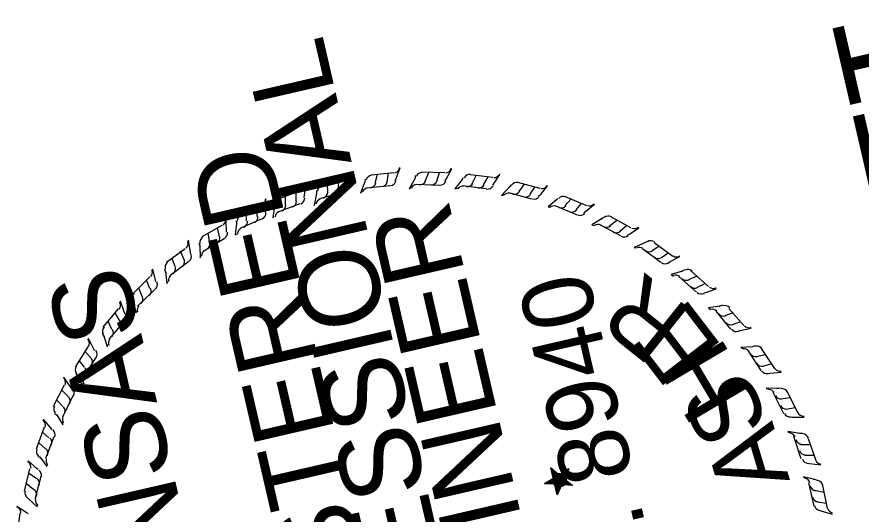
# Model space of a CAD drawing. Extents: x 634644 to 1109343, y 286699 to 700411.
# Drawn here: x 1108872.2 to 1108970.3, y 700241.6 to 700299.3 of the extents above; entities that cross this region are included whole.
import ezdxf

# ---------------------------------------------------------------- set-up
doc = ezdxf.new("R2010")
doc.units = 0
doc.layers.add('S_GAS_UTILITIES', color=7, linetype='Continuous')
doc.layers.add('S_PRIMARY_CTL', color=7, linetype='Continuous')

msp = doc.modelspace()

# ---------------------------------------------------------------- linework, layer by layer
at = {"layer": 'S_PRIMARY_CTL'}
for p, q in [((1108916.259, 700280.557), (1108916.717, 700281.771)), ((1108916.717, 700281.771), (1108916.555, 700281.672)), ((1108922.065, 700280.481), (1108922.712, 700281.677)), ((1108922.712, 700281.677), (1108922.537, 700281.637)), ((1108910.511, 700279.846), (1108910.768, 700281.136)), ((1108910.768, 700281.136), (1108910.651, 700281.109)), ((1108913.327, 700280.988), (1108915.98, 700281.231)), ((1108913.803, 700279.99), (1108914.055, 700281.033)), ((1108915.188, 700280.125), (1108915.368, 700281.213)), ((1108918.462, 700280.881), (1108918.471, 700280.575)), ((1108919.227, 700281.304), (1108921.889, 700281.241)), ((1108919.6, 700280.22), (1108920.041, 700281.245)), ((1108920.954, 700280.224), (1108921.278, 700281.223)), ((1108924.003, 700280.62), (1108923.926, 700280.418)), ((1108924.839, 700280.998), (1108927.497, 700280.688)), ((1108925.082, 700279.946), (1108925.536, 700280.913)), ((1108926.404, 700279.82), (1108926.931, 700280.742)), ((1108927.556, 700279.901), (1108928.289, 700280.994)), ((1108928.289, 700280.994), (1108928.172, 700280.967)), ((1108905.583, 700278.523), (1108905.708, 700279.845)), ((1108905.708, 700279.845), (1108905.605, 700279.76)), ((1108907.57, 700279.782), (1108910.161, 700280.565)), ((1108908.281, 700278.838), (1108908.258, 700280.003)), ((1108909.527, 700279.31), (1108909.589, 700280.372)), ((1108910.448, 700279.585), (1108910.511, 700279.846)), ((1108912.598, 700280.143), (1108912.095, 700278.856)), ((1108912.598, 700280.143), (1108912.567, 700280.012)), ((1108912.648, 700280.462), (1108912.598, 700280.143)), ((1108915.53, 700279.711), (1108912.76, 700279.441)), ((1108916.137, 700280.282), (1108916.259, 700280.557)), ((1108918.471, 700280.575), (1108917.765, 700279.365)), ((1108918.471, 700280.575), (1108918.381, 700280.431)), ((1108921.309, 700279.752), (1108918.516, 700279.846)), ((1108921.93, 700280.265), (1108922.065, 700280.481)), ((1108923.926, 700280.418), (1108923.063, 700279.357)), ((1108923.926, 700280.418), (1108923.895, 700280.288)), ((1108926.701, 700279.335), (1108923.972, 700279.69)), ((1108927.466, 700279.757), (1108927.556, 700279.901)), ((1108929.606, 700279.82), (1108929.472, 700279.605)), ((1108930.339, 700280.113), (1108932.961, 700279.425)), ((1108930.524, 700279.047), (1108931.135, 700279.866)), ((1108933.02, 700278.638), (1108933.825, 700279.686)), ((1108933.825, 700279.686), (1108933.649, 700279.645)), ((1108902.695, 700278.226), (1108905.245, 700279.184)), ((1108904.625, 700277.871), (1108904.629, 700278.919)), ((1108906.999, 700278.789), (1108906.698, 700277.426)), ((1108906.999, 700278.789), (1108906.954, 700278.717)), ((1108906.977, 700279.153), (1108906.999, 700278.789)), ((1108909.927, 700278.91), (1108907.323, 700278.186)), ((1108912.095, 700278.856), (1108912.301, 700279.027)), ((1108917.765, 700279.365), (1108917.972, 700279.536)), ((1108923.063, 700279.357), (1108923.355, 700279.424)), ((1108929.472, 700279.605), (1108928.478, 700278.575)), ((1108932.022, 700278.161), (1108929.328, 700278.894)), ((1108929.472, 700279.605), (1108929.368, 700279.519)), ((1108931.828, 700278.732), (1108932.381, 700279.537)), ((1108901.108, 700278.167), (1108901.005, 700278.082)), ((1108901.041, 700276.859), (1108901.108, 700278.167)), ((1108903.366, 700277.457), (1108903.37, 700278.505)), ((1108905.506, 700278.321), (1108905.583, 700278.523)), ((1108906.698, 700277.426), (1108906.819, 700277.7)), ((1108928.478, 700278.575), (1108928.77, 700278.642)), ((1108932.8, 700278.526), (1108933.02, 700278.638)), ((1108934.873, 700278.081), (1108933.897, 700277.24)), ((1108934.873, 700278.081), (1108934.783, 700277.937)), ((1108935.021, 700278.238), (1108934.873, 700278.081)), ((1108935.835, 700277.379), (1108936.577, 700278.166)), ((1108935.898, 700278.44), (1108938.354, 700277.406)), ((1108898.194, 700276.386), (1108900.6, 700277.434)), ((1108900.096, 700276.148), (1108900.042, 700277.182)), ((1108901.036, 700276.611), (1108901.041, 700276.859)), ((1108902.111, 700277.29), (1108901.913, 700276.013)), ((1108902.102, 700277.596), (1108902.111, 700277.29)), ((1108902.111, 700277.29), (1108902.138, 700277.174)), ((1108905.057, 700277.601), (1108902.507, 700276.643)), ((1108933.897, 700277.24), (1108934.086, 700277.222)), ((1108937.315, 700276.304), (1108934.729, 700277.37)), ((1108937.18, 700276.889), (1108937.805, 700277.649)), ((1108938.075, 700276.48), (1108938.268, 700276.709)), ((1108938.268, 700276.709), (1108939.303, 700277.564)), ((1108939.303, 700277.564), (1108939.127, 700277.523)), ((1108896.44, 700275.981), (1108896.364, 700275.779)), ((1108896.517, 700274.583), (1108896.44, 700275.981)), ((1108900.658, 700275.847), (1108898.136, 700274.772)), ((1108898.864, 700275.617), (1108898.81, 700276.652)), ((1108901.913, 700276.013), (1108902.075, 700276.112)), ((1108940.175, 700275.918), (1108938.997, 700275.153)), ((1108940.175, 700275.918), (1108940.085, 700275.774)), ((1108940.337, 700276.017), (1108940.175, 700275.918)), ((1108941.241, 700276.102), (1108943.503, 700274.839)), ((1108893.679, 700273.804), (1108896.017, 700275.145)), ((1108895.716, 700273.782), (1108895.473, 700274.834)), ((1108897.695, 700275.347), (1108897.511, 700274.012)), ((1108897.627, 700275.64), (1108897.695, 700275.347)), ((1108897.695, 700275.347), (1108897.722, 700275.23)), ((1108938.997, 700275.153), (1108939.258, 700275.09)), ((1108942.366, 700273.899), (1108939.914, 700275.18)), ((1108941.003, 700275.001), (1108941.889, 700275.698)), ((1108942.244, 700274.425), (1108943.013, 700275.095)), ((1108943.373, 700274.07), (1108944.434, 700274.808)), ((1108944.434, 700274.808), (1108944.304, 700274.839)), ((1108894.583, 700273.089), (1108894.385, 700274.214)), ((1108896.512, 700274.335), (1108896.517, 700274.583)), ((1108897.511, 700274.012), (1108897.789, 700274.138)), ((1108943.153, 700273.957), (1108943.373, 700274.07)), ((1108892.114, 700273.382), (1108891.979, 700273.166)), ((1108892.321, 700271.951), (1108892.114, 700273.382)), ((1108893.301, 700273.04), (1108893.427, 700272.761)), ((1108896.265, 700273.539), (1108893.882, 700272.127)), ((1108945.145, 700273.063), (1108943.913, 700272.532)), ((1108945.145, 700273.063), (1108945.028, 700273.036)), ((1108945.41, 700273.247), (1108945.145, 700273.063)), ((1108946.238, 700273.13), (1108948.392, 700271.534)), ((1108889.564, 700270.822), (1108891.718, 700272.428)), ((1108891.593, 700271.106), (1108891.174, 700272.118)), ((1108892.362, 700271.776), (1108892.321, 700271.951)), ((1108893.427, 700272.761), (1108893.396, 700272.631)), ((1108893.427, 700272.761), (1108893.445, 700271.349)), ((1108943.913, 700272.532), (1108944.102, 700272.514)), ((1108947.025, 700270.787), (1108944.871, 700272.384)), ((1108945.972, 700272.145), (1108946.827, 700272.712)), ((1108947.079, 700271.354), (1108947.875, 700271.907)), ((1108892.128, 700270.922), (1108889.929, 700269.244)), ((1108890.545, 700270.31), (1108890.185, 700271.335)), ((1108893.445, 700271.349), (1108893.567, 700271.623)), ((1108947.839, 700270.729), (1108948.104, 700270.913)), ((1108948.104, 700270.913), (1108949.206, 700271.476)), ((1108949.206, 700271.476), (1108949.134, 700271.521)), ((1108887.963, 700270.022), (1108887.815, 700269.864)), ((1108888.26, 700268.736), (1108887.963, 700270.022)), ((1108889.259, 700270.013), (1108889.443, 700269.748)), ((1108949.746, 700269.938), (1108949.539, 700269.767)), ((1108885.715, 700267.224), (1108887.613, 700269.14)), ((1108889.443, 700269.748), (1108889.578, 700268.362)), ((1108889.443, 700269.748), (1108889.47, 700269.631)), ((1108949.539, 700269.767), (1108948.208, 700269.398)), ((1108948.208, 700269.398), (1108948.496, 700269.218)), ((1108951.14, 700267.365), (1108949.121, 700269.177)), ((1108949.539, 700269.767), (1108949.364, 700269.726)), ((1108950.25, 700268.822), (1108951.144, 700269.214)), ((1108950.515, 700269.807), (1108952.534, 700267.995)), ((1108887.617, 700267.787), (1108887.213, 700268.74)), ((1108888.301, 700268.56), (1108888.26, 700268.736)), ((1108889.578, 700268.362), (1108889.7, 700268.637)), ((1108951.208, 700267.874), (1108952.089, 700268.323)), ((1108953.461, 700267.716), (1108953.303, 700267.865)), ((1108888.198, 700267.674), (1108886.183, 700265.731)), ((1108886.727, 700266.842), (1108886.322, 700267.795)), ((1108952.026, 700267.262), (1108952.26, 700267.316)), ((1108952.26, 700267.316), (1108953.461, 700267.716)), ((1108884.2, 700266.32), (1108884.065, 700266.104)), ((1108884.614, 700265.061), (1108884.2, 700266.32)), ((1108885.54, 700266.383), (1108885.697, 700266.235)), ((1108885.697, 700266.235), (1108885.666, 700266.104)), ((1108885.697, 700266.235), (1108885.994, 700264.949)), ((1108882.194, 700263.271), (1108883.979, 700265.407)), ((1108884.114, 700264.022), (1108883.593, 700264.948)), ((1108884.739, 700264.782), (1108884.614, 700265.061)), ((1108885.994, 700264.949), (1108886.143, 700265.106)), ((1108953.861, 700265.715), (1108952.548, 700265.535)), ((1108952.548, 700265.535), (1108952.777, 700265.342)), ((1108955.152, 700263.057), (1108953.443, 700265.126)), ((1108953.861, 700265.715), (1108953.758, 700265.63)), ((1108954.14, 700265.841), (1108953.861, 700265.715)), ((1108954.482, 700264.627), (1108955.449, 700264.973)), ((1108954.904, 700265.463), (1108956.659, 700263.467)), ((1108884.668, 700264.027), (1108882.824, 700261.877)), ((1108955.336, 700263.593), (1108956.303, 700263.939)), ((1108883.179, 700263.006), (1108882.788, 700263.901)), ((1108956.24, 700262.878), (1108957.527, 700263.175)), ((1108957.527, 700263.175), (1108957.383, 700263.264)), ((1108882.064, 700262.502), (1108882.248, 700262.237)), ((1108882.248, 700262.237), (1108882.649, 700261.036)), ((1108882.248, 700262.237), (1108882.32, 700262.192)), ((1108956.007, 700262.824), (1108956.24, 700262.878)), ((1108878.997, 700258.715), (1108880.436, 700261.018)), ((1108880.467, 700261.949), (1108880.378, 700261.805)), ((1108881.115, 700260.743), (1108880.467, 700261.949)), ((1108882.649, 700261.036), (1108882.784, 700261.252)), ((1108957.662, 700260.989), (1108956.321, 700260.926)), ((1108957.662, 700260.989), (1108957.486, 700260.948)), ((1108957.94, 700261.115), (1108957.662, 700260.989)), ((1108880.733, 700259.731), (1108880.063, 700260.5)), ((1108881.214, 700260.582), (1108881.115, 700260.743)), ((1108956.321, 700260.926), (1108956.537, 700260.791)), ((1108958.66, 700258.264), (1108957.145, 700260.562)), ((1108958.107, 700259.86), (1108959.159, 700260.103)), ((1108958.692, 700260.796), (1108960.207, 700258.498)), ((1108880, 700258.639), (1108879.388, 700259.421)), ((1108881.286, 700259.736), (1108879.802, 700257.361)), ((1108958.858, 700258.74), (1108959.838, 700259.028)), ((1108959.717, 700257.954), (1108960.985, 700258.062)), ((1108960.985, 700258.062), (1108960.886, 700258.223)), ((1108877.621, 700257.474), (1108877.603, 700257.285)), ((1108878.372, 700256.354), (1108877.621, 700257.474)), ((1108878.997, 700257.914), (1108879.11, 700257.694)), ((1108879.11, 700257.694), (1108879.744, 700256.547)), ((1108879.11, 700257.694), (1108879.254, 700257.604)), ((1108959.425, 700257.886), (1108959.717, 700257.954)), ((1108876.425, 700254.119), (1108877.707, 700256.57)), ((1108878.543, 700256.147), (1108878.372, 700256.354)), ((1108879.744, 700256.547), (1108879.879, 700256.763)), ((1108960.689, 700256.146), (1108959.263, 700256.186)), ((1108959.263, 700256.186), (1108959.537, 700256.065)), ((1108960.689, 700256.146), (1108960.513, 700256.105)), ((1108960.981, 700256.213), (1108960.689, 700256.146)), ((1108878.134, 700255.252), (1108877.347, 700255.994)), ((1108878.674, 700255.315), (1108877.464, 700252.819)), ((1108961.305, 700253.209), (1108960.055, 700255.691)), ((1108960.959, 700254.977), (1108962.038, 700255.103)), ((1108961.701, 700255.764), (1108962.938, 700253.34)), ((1108877.487, 700254.056), (1108876.816, 700254.825)), ((1108876.511, 700253.215), (1108876.785, 700253.093)), ((1108961.548, 700253.758), (1108962.614, 700253.942)), ((1108875.247, 700252.553), (1108875.171, 700252.351)), ((1108876.088, 700251.578), (1108875.247, 700252.553)), ((1108876.785, 700253.093), (1108877.478, 700251.96)), ((1108876.785, 700253.093), (1108876.812, 700252.976)), ((1108877.478, 700251.96), (1108877.482, 700252.207)), ((1108962.056, 700252.89), (1108962.317, 700252.827)), ((1108962.317, 700252.827), (1108963.671, 700252.832)), ((1108963.671, 700252.832), (1108963.513, 700252.98)), ((1108874.429, 700249.163), (1108875.378, 700251.722)), ((1108876.259, 700251.371), (1108876.088, 700251.578)), ((1108875.863, 700250.417), (1108875.162, 700251.056)), ((1108876.448, 700250.552), (1108875.486, 700248.052)), ((1108963.185, 700250.934), (1108961.777, 700251.163)), ((1108961.777, 700251.163), (1108961.993, 700251.028)), ((1108963.307, 700248.006), (1108962.466, 700250.583)), ((1108963.185, 700250.934), (1108963.055, 700250.965)), ((1108963.491, 700250.943), (1108963.185, 700250.934)), ((1108964.121, 700250.349), (1108965.02, 700247.786)), ((1108875.477, 700249.158), (1108874.703, 700249.842)), ((1108963.235, 700249.652), (1108964.399, 700249.675)), ((1108874.573, 700248.272), (1108874.834, 700248.209)), ((1108963.707, 700248.406), (1108964.755, 700248.402)), ((1108873.458, 700247.768), (1108873.44, 700247.579)), ((1108874.461, 700246.891), (1108873.458, 700247.768)), ((1108874.834, 700248.209), (1108875.643, 700247.103)), ((1108874.834, 700248.209), (1108874.874, 700248.034)), ((1108875.643, 700247.103), (1108875.661, 700247.292)), ((1108964.04, 700247.498), (1108964.301, 700247.435)), ((1108964.301, 700247.435), (1108965.623, 700247.309)), ((1108965.623, 700247.309), (1108965.537, 700247.413)), ((1108873.044, 700244.224), (1108873.674, 700246.833)), ((1108874.425, 700245.713), (1108873.548, 700246.311)), ((1108874.618, 700246.743), (1108874.461, 700246.891)), ((1108934.237, 700246.96), (1108935.186, 700245.517)), ((1108934.237, 700246.96), (1108934.723, 700245.656)), ((1108934.237, 700246.96), (1108934.826, 700245.741)), ((1108934.237, 700246.96), (1108934.885, 700245.755)), ((1108934.237, 700246.96), (1108934.934, 700246.074)), ((1108934.237, 700246.96), (1108934.966, 700246.205)), ((1108934.237, 700246.96), (1108935.011, 700246.277)), ((1108936.301, 700246.821), (1108935.078, 700245.984)), ((1108936.301, 700246.821), (1108935.105, 700245.867)), ((1108936.301, 700246.821), (1108935.186, 700245.517)), ((1108936.301, 700246.821), (1108935.339, 700245.921)), ((1108936.301, 700246.821), (1108935.483, 700245.831)), ((1108936.301, 700246.821), (1108935.537, 700245.597)), ((1108936.301, 700246.821), (1108935.654, 700245.624)), ((1108874.924, 700245.952), (1108874.25, 700243.271)), ((1108933.491, 700245.125), (1108934.534, 700245.674)), ((1108933.491, 700245.125), (1108934.534, 700245.674)), ((1108935.186, 700245.517), (1108933.491, 700245.125)), ((1108933.491, 700245.125), (1108934.575, 700245.498)), ((1108933.491, 700245.125), (1108934.602, 700245.382)), ((1108934.966, 700243.803), (1108935.186, 700245.517)), ((1108936.747, 700244.892), (1108935.186, 700245.517)), ((1108936.747, 700244.892), (1108935.537, 700245.597)), ((1108936.747, 700244.892), (1108935.546, 700245.292)), ((1108936.747, 700244.892), (1108935.577, 700245.422)), ((1108936.747, 700244.892), (1108935.64, 700245.683)), ((1108964.908, 700245.605), (1108963.604, 700245.919)), ((1108963.604, 700245.919), (1108963.761, 700245.771)), ((1108964.908, 700245.605), (1108964.733, 700245.564)), ((1108965.241, 700245.497), (1108964.908, 700245.605)), ((1108874.11, 700244.409), (1108873.278, 700245.079)), ((1108933.491, 700245.125), (1108934.642, 700245.206)), ((1108933.491, 700245.125), (1108934.656, 700245.148)), ((1108934.966, 700243.803), (1108934.871, 700245.013)), ((1108934.966, 700243.803), (1108935.411, 700245.076)), ((1108934.966, 700243.803), (1108935.294, 700245.049)), ((1108934.966, 700243.803), (1108934.988, 700245.04)), ((1108934.966, 700243.803), (1108935.236, 700245.035)), ((1108934.966, 700243.803), (1108935.002, 700244.981)), ((1108936.747, 700244.892), (1108935.353, 700245.062)), ((1108936.747, 700244.892), (1108935.501, 700245.22)), ((1108964.823, 700242.506), (1108964.202, 700245.195)), ((1108964.886, 700244.368), (1108965.988, 700244.13)), ((1108965.812, 700244.89), (1108966.361, 700242.245)), ((1108873.337, 700243.491), (1108873.494, 700243.343)), ((1108873.494, 700243.343), (1108874.511, 700242.408)), ((1108873.494, 700243.343), (1108873.638, 700243.253)), ((1108873.247, 700241.747), (1108872.154, 700242.479)), ((1108872.154, 700242.479), (1108872.181, 700242.363)), ((1108874.511, 700242.408), (1108874.515, 700242.655)), ((1108965.138, 700243.01), (1108966.284, 700242.844)), ((1108872.163, 700238.972), (1108872.518, 700241.702)), ((1108873.463, 700241.612), (1108873.247, 700241.747)), ((1108965.426, 700242.03), (1108965.628, 700241.953)), ((1108965.628, 700241.953), (1108966.946, 700241.58)), ((1108966.946, 700241.58), (1108966.847, 700241.742))]:
    msp.add_line(p, q, dxfattribs=at)
msp.add_lwpolyline([(1108933.491, 700245.125), (1108936.301, 700246.821), (1108934.966, 700243.803), (1108934.237, 700246.96), (1108936.747, 700244.892), (1108933.491, 700245.125)], dxfattribs=at)
for radius in [0.807, 0.731, 0.678, 0.622, 0.543, 0.504, 0.464, 0.4, 0.35, 0.291, 0.232, 0.173, 0.139, 0.0676]:
    msp.add_circle((1108935.238, 700245.524), radius, dxfattribs=at)
for centre, start, end in [((1108915.949, 700281.94), 280.57003, 339.35787), ((1108909.96, 700281.189), 291.03299, 349.82084), ((1108913.464, 700280.192), 96.30926, 164.68323), ((1108919.273, 700280.513), 89.18424, 157.55821), ((1108921.956, 700281.939), 273.44502, 332.23286), ((1108924.801, 700280.272), 82.90032, 151.2743), ((1108927.624, 700281.396), 267.1611, 325.94894), ((1108904.961, 700279.835), 294.43481, 353.22265), ((1108907.833, 700279.018), 106.77222, 175.14619), ((1108913.175, 700280.203), 276.30926, 344.68323), ((1108914.49, 700280.343), 276.30926, 344.68323), ((1108915.51, 700280.459), 276.30926, 344.68323), ((1108918.653, 700279.097), 93.44502, 152.23286), ((1108918.988, 700280.559), 269.18424, 337.55821), ((1108920.31, 700280.535), 269.18424, 337.55821), ((1108921.336, 700280.524), 269.18424, 337.55821), ((1108924.029, 700278.932), 87.1611, 145.94894), ((1108924.523, 700280.349), 262.90032, 331.2743), ((1108925.834, 700280.181), 262.90032, 331.2743), ((1108926.853, 700280.057), 262.90032, 331.2743), ((1108930.264, 700279.351), 75.85415, 144.22812), ((1108933.204, 700280.12), 260.11492, 318.90277), ((1108907.547, 700278.977), 286.77222, 355.14619), ((1108908.814, 700279.354), 286.77222, 355.14619), ((1108909.796, 700279.653), 286.77222, 355.14619), ((1108913.024, 700278.71), 100.57003, 159.35787), ((1108929.334, 700278.116), 80.11492, 138.90277), ((1108929.997, 700279.462), 255.85415, 324.22812), ((1108931.278, 700279.134), 255.85415, 324.22812), ((1108900.324, 700278.083), 298.79119, 357.57904), ((1108902.966, 700277.542), 110.17403, 178.548), ((1108903.926, 700277.935), 290.17403, 358.548), ((1108904.889, 700278.291), 290.17403, 358.548), ((1108907.669, 700277.482), 111.03299, 169.82084), ((1108932.274, 700278.886), 255.85415, 324.22812), ((1108935.682, 700277.725), 68.46542, 136.83939), ((1108902.684, 700277.483), 290.17403, 358.548), ((1108934.602, 700276.621), 72.7262, 131.51404), ((1108935.433, 700277.87), 248.46542, 316.83939), ((1108936.66, 700277.38), 248.46542, 316.83939), ((1108938.697, 700278.11), 252.7262, 311.51404), ((1108895.69, 700275.741), 305.09384, 3.88168), ((1108898.51, 700275.645), 114.53042, 182.90439), ((1108899.437, 700276.11), 294.53042, 2.90439), ((1108900.369, 700276.539), 294.53042, 2.90439), ((1108902.894, 700275.998), 114.43481, 173.22265), ((1108937.616, 700277.006), 248.46542, 316.83939), ((1108940.911, 700275.44), 61.52137, 129.89535), ((1108898.555, 700274.1), 118.79119, 177.57904), ((1108898.232, 700275.566), 294.53042, 2.90439), ((1108939.705, 700274.474), 65.78215, 124.56999), ((1108940.681, 700275.614), 241.52137, 309.89535), ((1108943.95, 700275.458), 245.78215, 304.56999), ((1108894.155, 700273.118), 120.83306, 189.20703), ((1108895.025, 700273.682), 300.83306, 9.20703), ((1108895.905, 700274.21), 300.83306, 9.20703), ((1108941.84, 700274.979), 241.52137, 309.89535), ((1108942.744, 700274.492), 241.52137, 309.89535), ((1108891.317, 700273.007), 312.14508, 10.93292), ((1108893.888, 700273.008), 300.83306, 9.20703), ((1108945.852, 700272.58), 53.5218, 121.89577), ((1108894.369, 700271.588), 125.09384, 183.88168), ((1108944.523, 700271.792), 57.78258, 116.57042), ((1108945.648, 700272.784), 233.5218, 301.89577), ((1108890.114, 700270.215), 127.8843, 196.25827), ((1108890.909, 700270.881), 307.8843, 16.25827), ((1108891.718, 700271.514), 307.8843, 16.25827), ((1108946.708, 700271.994), 233.5218, 301.89577), ((1108948.865, 700272.175), 237.78258, 296.57042), ((1108887.171, 700269.636), 319.00344, 17.79128), ((1108889.863, 700270.074), 307.8843, 16.25827), ((1108947.536, 700271.386), 233.5218, 301.89577), ((1108950.166, 700269.232), 47.65263, 116.0266), ((1108890.516, 700268.723), 132.14508, 190.93292), ((1108948.763, 700268.583), 51.91341, 110.70125), ((1108949.984, 700269.455), 227.65263, 296.0266), ((1108887.748, 700268.203), 314.74266, 23.11663), ((1108950.957, 700268.561), 227.65263, 296.0266), ((1108953.121, 700268.52), 231.91341, 290.70125), ((1108886.311, 700266.721), 134.74266, 203.11663), ((1108887.021, 700267.478), 314.74266, 23.11663), ((1108951.718, 700267.872), 227.65263, 296.0266), ((1108883.457, 700265.822), 323.95049, 22.73834), ((1108886.078, 700266.551), 314.74266, 23.11663), ((1108886.888, 700265.288), 139.00344, 197.79128), ((1108952.974, 700264.616), 44.09939, 102.88724), ((1108954.452, 700265.068), 39.83862, 108.21259), ((1108883.493, 700263.658), 319.68972, 28.06369), ((1108884.155, 700264.443), 319.68972, 28.06369), ((1108954.302, 700265.314), 219.83862, 288.21259), ((1108882.851, 700262.843), 139.68972, 208.06369), ((1108882.634, 700262.653), 319.68972, 28.06369), ((1108955.145, 700264.296), 219.83862, 288.21259), ((1108955.805, 700263.51), 219.83862, 288.21259), ((1108957.283, 700263.961), 224.09939, 282.88724), ((1108879.842, 700261.392), 332.22624, 31.01408), ((1108883.549, 700261.465), 143.95049, 202.73834), ((1108958.164, 700260.336), 33.47236, 101.84634), ((1108880.731, 700260.128), 327.96546, 36.33943), ((1108956.645, 700260.051), 37.73314, 96.52098), ((1108958.042, 700260.597), 213.47236, 281.84634), ((1108880.189, 700259.256), 327.96546, 36.33943), ((1108958.767, 700259.492), 213.47236, 281.84634), ((1108879.671, 700258.357), 147.96546, 216.33943), ((1108879.483, 700258.138), 327.96546, 36.33943), ((1108959.335, 700258.637), 213.47236, 281.84634), ((1108960.854, 700258.922), 217.73314, 276.52098), ((1108877.075, 700256.815), 337.451, 36.23884), ((1108880.56, 700257.093), 152.22624, 211.01408), ((1108878.075, 700255.637), 333.19023, 41.5642), ((1108961.074, 700255.416), 26.90662, 95.2806), ((1108877.615, 700254.72), 333.19023, 41.5642), ((1108959.532, 700255.306), 31.1674, 89.95524), ((1108960.983, 700255.69), 206.90662, 275.2806), ((1108961.577, 700254.509), 206.90662, 275.2806), ((1108877.181, 700253.777), 153.19023, 221.5642), ((1108877.014, 700253.542), 333.19023, 41.5642), ((1108962.044, 700253.595), 206.90662, 275.2806), ((1108963.585, 700253.704), 211.1674, 269.95524), ((1108874.738, 700251.877), 343.43436, 42.22221), ((1108878.182, 700252.6), 157.451, 216.23884), ((1108875.856, 700250.81), 339.17359, 47.54756), ((1108875.494, 700249.849), 339.17359, 47.54756), ((1108961.925, 700250.263), 22.92492, 81.71276), ((1108963.416, 700250.435), 198.66414, 267.03812), ((1108963.467, 700250.151), 18.66414, 87.03812), ((1108875.161, 700248.867), 159.17359, 227.54756), ((1108875.019, 700248.615), 339.17359, 47.54756), ((1108963.834, 700249.181), 198.66414, 267.03812), ((1108873.047, 700247.017), 350.33158, 49.11942), ((1108876.279, 700247.8), 163.43436, 222.22221), ((1108964.165, 700248.209), 198.66414, 267.03812), ((1108965.707, 700248.097), 202.92492, 261.71276), ((1108874.285, 700246.092), 346.0708, 54.44478), ((1108874.041, 700245.095), 346.0708, 54.44478), ((1108963.606, 700245.018), 16.42361, 75.21146), ((1108965.125, 700244.732), 12.16284, 80.53681), ((1108873.718, 700243.813), 346.0708, 54.44478), ((1108965.106, 700245.02), 192.16284, 260.53681), ((1108873.828, 700244.08), 166.0708, 234.44478), ((1108965.38, 700243.726), 192.16284, 260.53681), ((1108875.066, 700243.155), 170.33158, 229.11942), ((1108965.599, 700242.724), 192.16284, 260.53681), ((1108871.882, 700241.722), 356.35627, 55.14411), ((1108967.118, 700242.437), 196.42361, 255.21146)]:
    msp.add_arc(centre, 0.74, start, end, dxfattribs=at)

# ---------------------------------------------------------------- texts
at = {"layer": 'S_GAS_UTILITIES'}
msp.add_text('TEMPORARY EROSION CONTROL DETAILS', height=12.05241, rotation=103, dxfattribs=at).set_placement((1109046.318, 700007.877))
at = {"layer": 'S_PRIMARY_CTL'}
for s, height, rotation, p in [('PROFESSIONAL', 9.37438, 103, (1108929.573, 700202.348)), ('REGISTERED', 9.3744, 103, (1108919.648, 700205.598)), ('ENGINEER', 9.3744, 103, (1108936.983, 700214.527)), ('ARKANSAS', 9.3744, 103, (1108900.063, 700204.279)), ('No. 8940', 8.2357, 103, (1108948.437, 700226.531)), ('R', 8.203, 141.39464, (1108950.88, 700265.027)), ('E', 8.203, 127.5342, (1108954.311, 700260.831)), ('H', 8.201, 120.60399, (1108957.797, 700255.601)), ('S', 8.203, 113.67377, (1108959.695, 700251.914)), ('A', 8.203, 106.74355, (1108962.039, 700245.497))]:
    msp.add_text(s, height=height, rotation=rotation, dxfattribs=at).set_placement(p)

doc.saveas('drawing.dxf')
